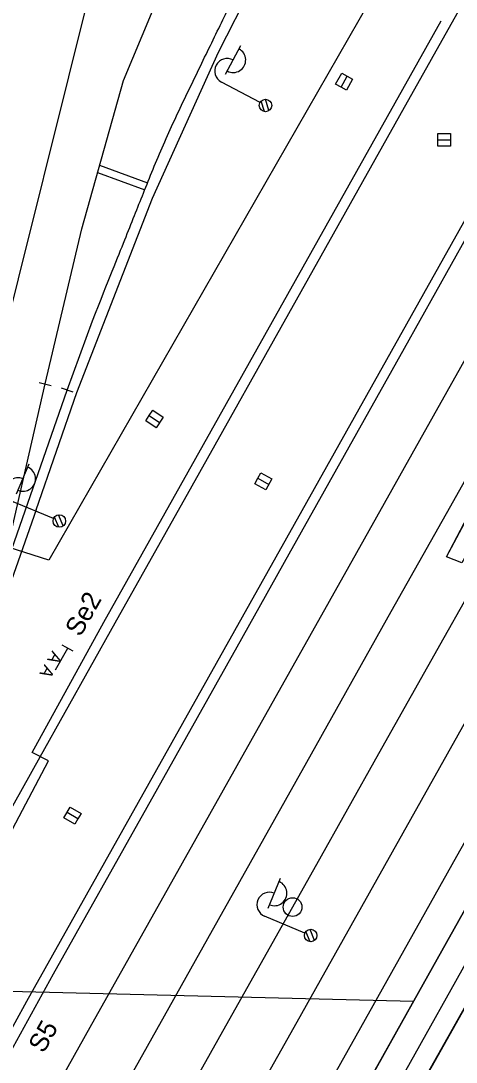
# Model space of a CAD drawing. Extents: x -781083 to -763634, y -1029516 to -1022695.
# Drawn here: x -765155.8 to -765121, y -1024152.2 to -1024068.9 of the extents above; entities that cross this region are included whole.
import ezdxf

# ---------------------------------------------------------------- set-up
doc = ezdxf.new("R2010")
doc.units = 0
for name, color, linetype in [('Hranice parcel', 7, 'Continuous'), ('PS120111-MOK', 7, 'Continuous'), ('PS_12-01-10_Kabelizace_nove_kabelizace', 7, 'Continuous'), ('PS_12-01-11_SZZ_Slany_rusene_prvky', 7, 'Continuous'), ('PS_12-01-11_SZZ_Slany_rusene_prvky_popis', 7, 'Continuous'), ('SO128401_EOV_trasa', 7, 'Continuous'), ('Vrstva 1', 7, 'Continuous'), ('Vrstva 12', 7, 'Continuous'), ('Vrstva 14_nástupiště', 7, 'Continuous'), ('Vrstva 16', 7, 'Continuous'), ('Vrstva 2', 7, 'Continuous'), ('Vrstva 25', 7, 'Continuous'), ('Vrstva 33', 7, 'Continuous'), ('Vrstva 4', 7, 'Continuous'), ('Vrstva 43', 7, 'Continuous'), ('Vrstva 7', 7, 'Continuous'), ('ČD Telematika_TK', 7, 'Continuous')]:
    doc.layers.add(name, color=color, linetype=linetype)

# ---------------------------------------------------------------- blocks, each defined once
blk = doc.blocks.new('C084')
at = {"layer": 'Vrstva 2'}
blk.add_line((0, 5), (0, -5), dxfattribs=at)
blk = doc.blocks.new('C669_4')
at = {"layer": 'Vrstva 25'}
for p, q in [((0, 5), (0, 40)), ((7, 40), (33, 40)), ((-4.78, -1.46), (1.44, 4.76)), ((-2.39, -4.37), (4.38, 2.4))]:
    blk.add_line(p, q, dxfattribs=at)
blk.add_circle((0, 0), 5, dxfattribs=at)
blk.add_circle((0, 0), 5, dxfattribs=at)
for centre, start, end in [((10, 40), 0, 180), ((20, 39.88), 179.29742, 0.70257)]:
    blk.add_arc(centre, 10, start, end, dxfattribs=at)
blk = doc.blocks.new('C669_17')
at = {"layer": 'Vrstva 25'}
for p, q in [((0, 5), (0, 40)), ((6.99, 40), (33, 40)), ((-4.78, -1.46), (1.44, 4.76)), ((-2.39, -4.37), (4.38, 2.4))]:
    blk.add_line(p, q, dxfattribs=at)
blk.add_circle((0, 0), 5, dxfattribs=at)
blk.add_circle((0, 0), 5, dxfattribs=at)
for centre, start, end in [((10, 40), 359.99996, 179.99996), ((20, 39.88), 179.29739, 0.70254)]:
    blk.add_arc(centre, 10, start, end, dxfattribs=at)
blk = doc.blocks.new('C669_26')
at = {"layer": 'Vrstva 25'}
for p, q in [((0, 5), (0.01, 40)), ((7, 40), (33, 40)), ((-4.78, -1.46), (1.44, 4.76)), ((-2.38, -4.37), (4.38, 2.4))]:
    blk.add_line(p, q, dxfattribs=at)
blk.add_circle((0, 0), 5, dxfattribs=at)
blk.add_circle((0, 0), 5, dxfattribs=at)
for centre, start, end in [((10, 40), 359.99985, 179.99985), ((20, 39.88), 179.29727, 0.70242)]:
    blk.add_arc(centre, 10, start, end, dxfattribs=at)
blk = doc.blocks.new('C154_1')
at = {"layer": 'Vrstva 43'}
blk.add_lwpolyline([(-5, 0), (-5, 5), (5, 5), (5, -5), (-5, -5), (-5, 0), (5, 0)], dxfattribs=at)
blk = doc.blocks.new('C513_19')
at = {"layer": 'Vrstva 7'}
blk.add_circle((0, 0), 7.5, dxfattribs=at)
blk = doc.blocks.new('C016_15')
at = {"layer": 'PS_12-01-11_SZZ_Slany_rusene_prvky'}
for p, q in [((0, 5), (0, -5)), ((19.8, 0), (0, 0))]:
    blk.add_line(p, q, dxfattribs=at)

msp = doc.modelspace()

# ---------------------------------------------------------------- linework, layer by layer
at = {"layer": 'Hranice parcel'}
for points in [[(-765116.35, -1024047.19), (-765153.59, -1024112.04), (-765161.39, -1024109.58), (-765173.08, -1024143.22), (-765187.69, -1024156.25)], [(-765167.98, -1024240.28), (-765163.25, -1024232.1), (-765166.67, -1024230.28), (-765110.28, -1024130.11), (-765108.75, -1024130.98)]]:
    msp.add_lwpolyline(points, dxfattribs=at)
at = {"layer": 'PS120111-MOK'}
msp.add_lwpolyline([(-765225.805, -1024328.474), (-765227.041, -1024327.403), (-765189.607, -1024263.284), (-765167.089, -1024223.521), (-765111.836, -1024124.939), (-765108.851, -1024119.501), (-765085.73, -1024077.899), (-765081.023, -1024080.523), (-765060.822, -1024044.042), (-765057.835, -1024038.647), (-765021.888, -1023965.037), (-765009.529, -1023945.01), (-764990.029, -1023909.994), (-764973.93, -1023884.565), (-764957.796, -1023847.878), (-764953.349, -1023837.037), (-764952.504, -1023834.976), (-764951.393, -1023835.06)], dxfattribs=at)
at = {"layer": 'PS_12-01-10_Kabelizace_nove_kabelizace'}
msp.add_lwpolyline([(-765057.835, -1024038.647), (-765081.023, -1024080.523), (-765085.73, -1024077.899), (-765108.851, -1024119.501), (-765111.836, -1024124.939), (-765167.089, -1024223.521), (-765189.607, -1024263.284)], dxfattribs=at)
at = {"layer": 'SO128401_EOV_trasa'}
msp.add_lwpolyline([(-765111.624, -1024019.292), (-765109.87, -1024016.203), (-765060.824, -1024044.045), (-765060.824, -1024044.045), (-765081.023, -1024080.523), (-765081.023, -1024080.523), (-765085.73, -1024077.899), (-765108.851, -1024119.501), (-765111.836, -1024124.939), (-765167.089, -1024223.521), (-765176.711, -1024240.445), (-765189.607, -1024263.284), (-765189.607, -1024263.284), (-765225.916, -1024325.475), (-765224.46, -1024326.168)], dxfattribs=at)
at = {"layer": 'Vrstva 1'}
for p, q in [((-765152.11, -1024098.437), (-765150.097, -1024092.883)), ((-765157.604, -1024114.168), (-765153.884, -1024097.947))]:
    msp.add_line(p, q, dxfattribs=at)
for points in [[(-765132.595, -1024166.323), (-765129.154, -1024160.282), (-765120.123, -1024144.179), (-765113.641, -1024132.601), (-765108.378, -1024123.125), (-765107.852, -1024122.175), (-765106.668, -1024120.081), (-765061.822, -1024040.141), (-765060.629, -1024038.009), (-765057.197, -1024031.875), (-765051.942, -1024022.391), (-765050.753, -1024020.205), (-765046.155, -1024011.44), (-765043.134, -1024005.303), (-765039.745, -1023997.951), (-765035.047, -1023987.211), (-765027.653, -1023970.046)], [(-765188.123, -1024215.705), (-765183.275, -1024205.436), (-765176.4, -1024194.792), (-765173.261, -1024189.785), (-765169.195, -1024182.942), (-765164.586, -1024174.885), (-765158.873, -1024164.755), (-765150.27, -1024149.435), (-765143.977, -1024138.227), (-765137.411, -1024126.534), (-765129.538, -1024112.519), (-765123.879, -1024102.438), (-765115.14, -1024086.868), (-765106.342, -1024071.201), (-765098.535, -1024057.295), (-765090.39, -1024042.796), (-765081.493, -1024026.948), (-765072.655, -1024011.193), (-765066.823, -1024000.8), (-765059.521, -1023987.798)], [(-765148.415, -1024155.812), (-765140.866, -1024142.346), (-765132.943, -1024128.227), (-765126.171, -1024116.166), (-765121.754, -1024108.312), (-765113.478, -1024093.598), (-765104.781, -1024078.127), (-765095.839, -1024062.211), (-765085.058, -1024043.024), (-765076.707, -1024028.176), (-765070.056, -1024016.362), (-765061.157, -1024000.548), (-765054.406, -1023988.525)], [(-765146.757, -1024162.404), (-765139.177, -1024148.91), (-765132.143, -1024136.38), (-765127.156, -1024127.518), (-765121.934, -1024118.232), (-765120.315, -1024115.353), (-765119.12, -1024113.223), (-765112.669, -1024101.733), (-765103.973, -1024086.276), (-765096.294, -1024072.637), (-765095.105, -1024070.517), (-765089.672, -1024060.842), (-765082.163, -1024047.436), (-765074.191, -1024033.212), (-765072.982, -1024031.058), (-765064.275, -1024015.552), (-765063.062, -1024013.382), (-765057.199, -1024002.967), (-765051.483, -1023992.806)], [(-765138.578, -1024157.675), (-765133.719, -1024149), (-765131.846, -1024145.662), (-765126.088, -1024135.402), (-765117.89, -1024120.799), (-765116.125, -1024117.657), (-765114.927, -1024115.52), (-765098.436, -1024086.158), (-765092.138, -1024074.961), (-765090.925, -1024072.798), (-765083.437, -1024059.463), (-765075.468, -1024045.285), (-765069.982, -1024035.533), (-765068.774, -1024033.384), (-765060.064, -1024017.884), (-765058.869, -1024015.756), (-765052.709, -1024004.781), (-765046.025, -1023992.89)], [(-765173.904, -1024229.916), (-765173.254, -1024228.763), (-765165.873, -1024215.668), (-765157.715, -1024201.193), (-765150.799, -1024188.931), (-765144.602, -1024177.925), (-765137.347, -1024165.014), (-765128.994, -1024150.127), (-765120.916, -1024135.756), (-765114.604, -1024124.554), (-765112.054, -1024120.015), (-765110.861, -1024117.895), (-765104.54, -1024106.641), (-765100.051, -1024098.661), (-765087.977, -1024077.275), (-765086.765, -1024075.13), (-765078.232, -1024059.989), (-765070.151, -1024045.656), (-765065.795, -1024037.884), (-765064.623, -1024035.796), (-765055.87, -1024020.2), (-765054.667, -1024018.056), (-765047.51, -1024005.326), (-765040.997, -1023993.749)], [(-765188.645, -1024216.807), (-765188.123, -1024215.705), (-765183.275, -1024205.436), (-765177.884, -1024194.018), (-765175.294, -1024188.539), (-765171.011, -1024179.395), (-765166.902, -1024170.85), (-765161.865, -1024161.015), (-765157.64, -1024153.172), (-765153.216, -1024145.159), (-765145.723, -1024131.826), (-765138.513, -1024118.992), (-765134.338, -1024111.53), (-765125.127, -1024095.069), (-765118.846, -1024083.871), (-765111.182, -1024070.221), (-765102.382, -1024054.5), (-765092.788, -1024037.408), (-765084.151, -1024022.024), (-765076.991, -1024009.249), (-765068.63, -1023994.356)], [(-765172.246, -1024162.211), (-765170.819, -1024159.202), (-765168.619, -1024154.608), (-765165.549, -1024148.41), (-765161.235, -1024140.222), (-765154.293, -1024127.793), (-765148.27, -1024117.071), (-765142.114, -1024106.107), (-765133.762, -1024091.214), (-765125.489, -1024076.462), (-765117.884, -1024062.902), (-765110.768, -1024050.233), (-765105.763, -1024041.325), (-765098.173, -1024027.797), (-765093.751, -1024020.006), (-765089.847, -1024013.451), (-765084.177, -1024004.448), (-765080.239, -1023998.483)], [(-765153.884, -1024097.947), (-765150.951, -1024085.517), (-765147.606, -1024073.641), (-765143.001, -1024062.591), (-765137.715, -1024051.792), (-765128.609, -1024033.81)], [(-765161.079, -1024124.115), (-765157.604, -1024114.168), (-765152.11, -1024098.437)]]:
    msp.add_lwpolyline(points, dxfattribs=at)
msp.add_open_spline([(-765150.097, -1024092.883), (-765148.747, -1024089.508), (-765147.398, -1024086.134), (-765146.048, -1024082.759), (-765144.457, -1024078.78), (-765142.624, -1024074.903), (-765140.749, -1024071.046), (-765139.006, -1024067.459), (-765137.237, -1024063.889), (-765135.316, -1024060.397), (-765131.837, -1024054.072), (-765128.357, -1024047.746), (-765124.878, -1024041.421)], degree=3, dxfattribs=at)
at = {"layer": 'Vrstva 12'}
msp.add_lwpolyline([(-765141.624, -1024185.717), (-765112.98, -1024134.86), (-765111.428, -1024135.738)], dxfattribs=at)
at = {"layer": 'Vrstva 14_nástupiště'}
for points in [[(-765120.516, -1024112.26), (-765121.751, -1024111.784), (-765120.307, -1024109.085), (-765107.339, -1024086.102), (-765088.238, -1024052.011), (-765068.82, -1024017.519), (-765066.773, -1024014.026), (-765065.74, -1024014.645), (-765067.692, -1024018.181), (-765087.019, -1024052.666), (-765106.272, -1024086.911), (-765119.108, -1024109.781), (-765120.516, -1024112.26)], [(-765121.751, -1024111.784), (-765120.328, -1024109.099), (-765107.367, -1024086.112), (-765088.238, -1024052.012), (-765068.84, -1024017.518), (-765066.773, -1024014.026)]]:
    msp.add_lwpolyline(points, dxfattribs=at)
at = {"layer": 'Vrstva 16'}
for points in [[(-765133.915, -1024109.156), (-765093.624, -1024037.277)], [(-765154.6, -1024108.021), (-765151.34, -1024098.623), (-765145.3, -1024083.085), (-765140.01, -1024071.378), (-765134.622, -1024060.779), (-765125.778, -1024044.633), (-765124.866, -1024045.006), (-765123.958, -1024043.481)], [(-765158.455, -1024045.302), (-765145.435, -1024049.808), (-765149.98, -1024065.19), (-765158.103, -1024097.659)], [(-765154.913, -1024127.442), (-765149.172, -1024117.016), (-765122.169, -1024068.876)], [(-765154.6, -1024108.021), (-765166.182, -1024140.979), (-765167.55, -1024140.544)], [(-765163.385, -1024162.077), (-765160.054, -1024155.883), (-765155.345, -1024147.363), (-765133.915, -1024109.156)], [(-765169.807, -1024158.785), (-765153.62, -1024128.124)]]:
    msp.add_lwpolyline(points, dxfattribs=at)
at = {"layer": 'Vrstva 2'}
msp.add_line((-765157.604, -1024114.168), (-765153.884, -1024097.947), dxfattribs=at)
msp.add_lwpolyline([(-765161.079, -1024124.115), (-765157.604, -1024114.168), (-765152.11, -1024098.437)], dxfattribs=at)
at = {"layer": 'Vrstva 33'}
msp.add_lwpolyline([(-765199.732, -1024142.95), (-765194.595, -1024145.62), (-765124.39, -1024147.339)], dxfattribs=at)
at = {"layer": 'Vrstva 4'}
msp.add_lwpolyline([(-765153.62, -1024128.124), (-765154.913, -1024127.442)], dxfattribs=at)
at = {"layer": 'Vrstva 7'}
for p, q in [((-765149.521, -1024080.441), (-765145.677, -1024081.843)), ((-765149.684, -1024081.02), (-765145.903, -1024082.399))]:
    msp.add_line(p, q, dxfattribs=at)
at = {"layer": 'ČD Telematika_TK'}
msp.add_lwpolyline([(-765257.028, -1024404.569), (-765256.037, -1024398.213), (-765249.421, -1024374.188), (-765226.425, -1024328.292), (-765185.224, -1024255.545), (-765167.149, -1024223.486), (-765171.928, -1024220.746), (-765141.483, -1024166.52), (-765136.718, -1024169.454), (-765086.954, -1024080.425), (-765063.726, -1024094.284), (-765054.277, -1024080.444), (-765052.94, -1024078.307), (-765049.809, -1024079.983), (-765033.351, -1024048.633), (-765033.134, -1024014.623), (-765034.915, -1024000.619), (-765019.65, -1023968.646), (-765007.996, -1023946.352)], dxfattribs=at)

# ---------------------------------------------------------------- block references
at = {"layer": 'PS_12-01-11_SZZ_Slany_rusene_prvky', "xscale": 0.09999999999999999, "yscale": 0.09999999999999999, "rotation": -119.3247606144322}
msp.add_blockref('C016_15', (-765152.073, -1024119.099), dxfattribs=at)
at = {"layer": 'Vrstva 2'}
for p, xscale, yscale, rotation in [((-765153.884, -1024097.947), 0.09999999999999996, 0.09999999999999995, 77.08357253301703), ((-765152.11, -1024098.437), 0.09999999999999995, 0.09999999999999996, -109.09671589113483)]:
    msp.add_blockref('C084', p, dxfattribs=dict(at, xscale=xscale, yscale=yscale, rotation=rotation))
at = {"layer": 'Vrstva 25'}
for name, p, xscale, yscale, rotation in [('C669_4', (-765136.238, -1024075.648), 0.09999999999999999, 0.09999999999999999, 62.08811503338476), ('C669_26', (-765152.749, -1024108.919), 0.09999999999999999, 0.1, 67.27633765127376), ('C669_17', (-765132.622, -1024142.098), 0.09999999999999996, 0.09999999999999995, 67.24700124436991)]:
    msp.add_blockref(name, p, dxfattribs=dict(at, xscale=xscale, yscale=yscale, rotation=rotation))
at = {"layer": 'Vrstva 43'}
for p, xscale, yscale, rotation in [((-765129.946, -1024073.747), 0.10000000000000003, 0.10000000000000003, 60.65839346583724), ((-765145.131, -1024100.749), 0.1, 0.09999999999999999, -33.98665430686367), ((-765136.417, -1024105.736), 0.10000000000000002, 0.1, -29.31807632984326), ((-765151.691, -1024132.497), 0.1, 0.09999999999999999, 149.349952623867)]:
    msp.add_blockref('C154_1', p, dxfattribs=dict(at, xscale=xscale, yscale=yscale, rotation=rotation))
at = {"layer": 'Vrstva 43', "xscale": 0.1, "yscale": 0.10000000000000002}
msp.add_blockref('C154_1', (-765121.939, -1024078.404), dxfattribs=at)
at = {"layer": 'Vrstva 7', "xscale": 0.09999999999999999, "yscale": 0.09999999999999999, "rotation": 60.691330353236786}
msp.add_blockref('C513_19', (-765134.073, -1024139.819), dxfattribs=at)

# ---------------------------------------------------------------- texts
at = {"layer": 'PS_12-01-11_SZZ_Slany_rusene_prvky'}
msp.add_text('  A A ', height=1, rotation=240.67524, dxfattribs=at).set_placement((-765152.945, -1024118.609))
at = {"layer": 'PS_12-01-11_SZZ_Slany_rusene_prvky_popis'}
for s, rotation, p in [('Se2', 60.67524, (-765151.06, -1024118.259)), ('S5', 60.68626, (-765154.003, -1024151.591))]:
    msp.add_text(s, height=1.5, rotation=rotation, dxfattribs=at).set_placement(p)

doc.saveas('drawing.dxf')
